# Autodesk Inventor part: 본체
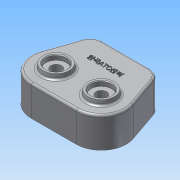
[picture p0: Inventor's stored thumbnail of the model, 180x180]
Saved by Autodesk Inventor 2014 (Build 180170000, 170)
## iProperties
Created: 2014-12
Part Number: 본체
Material: 알루미늄 6061
Document SubType Name: Modeling
Designer: user
Density: 2.71 g/cm^3
Appearance: 알루미늄 - 평지
Mass: 613.436 g
Surface Area: 665.181 cm^2
Volume: 226.36 cm^3
Author: user
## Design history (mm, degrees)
sketch "스케치1"
  geometry: L1 (-47, 0)-(47, 0); L2 (0, -36)-(0, -82); L3 (0, -36)-(-32.527, -68.527); L4 (0, -36)-(32.527, -68.527); L5 (-32.527, -104.527)-(32.527, -104.527); L6 (-66.565, -56.803)-(-47, 0); L7 (66.565, -56.803)-(47, 0); A1 r 46 centre (0, -36) between (0, -82) and (-32.527, -68.527); A2 r 36 centre (-32.527, -68.527) between (-66.565, -56.803) and (-32.527, -104.527); A3 r 36 centre (32.527, -68.527) between (32.527, -104.527) and (66.565, -56.803); A4 r 18 centre (-34.162, -18) between (-34.162, 0) and (-51.181, -12.138); A5 r 18 centre (34.162, -18) between (51.181, -12.138) and (34.162, 0); 2 further points
  constraints: 14 end point, 10 point on circle, 8 tangent, 5 centre point, 4 point on line, 3 coincident, 2 perpendicular, 1 horizontal, 1 midpoint, 1 vertical alignment
  dimensions: "d0" = 94 distance of L1.start L1.end; "d1" = 46 radius of A1; "d2" = 36 distance of L2.start point (0, 0); "d6" = 90 deg angle of L4 L3; "d7" = 45 deg angle of L4 L2; "d8" = 36 radius of A2; "d9" = 36 radius of A3; "d10" = 18 radius of A4; "d11" = 18 radius of A5
extrude "돌출1" new body sketch "스케치1" distance "d12" = 44; taper "d13" = 0 deg
sketch "스케치2"
  geometry: C1 r 20 at (-32.527, -68.527); C2 r 20 at (32.527, -68.527); A1 r 36 centre (-32.527, -68.527) between (-66.565, -56.803) and (-32.527, -104.527) reference; A2 r 36 centre (32.527, -68.527) between (32.527, -104.527) and (66.565, -56.803) reference; 1 further point
  constraints: 2 centre point, 2 coincident
  dimensions: "d14" = 40 diameter of C1; "d15" = 40 diameter of C2
extrude "돌출2" join sketch "스케치2" distance "d16" = 7; taper "d17" = 0 deg
node "작업 평면2"
  node "작업 평면1"
sketch "스케치3"
  geometry: L1 (-20, 44)-(-20, 51) reference; L2 (-20, 44)-(-18.766, 51); L3 (20, 51)-(-20, 51) reference; L4 (0, 51)-(0, 12.352); L5 (-18.654, 44)-(-34.038, 44) reference; L6 (-20, 51)-(-18.766, 51); L7 (-20, 51)-(-20, 44); 1 further point
  constraints: 8 end point, 2 perpendicular, 1 midpoint, 1 point on line
  dimensions: "d19" = 100 deg angle of L2 L5
revolve "회전1" sketch "스케치3" stored, may be unused: angle "d20" = 90 deg
sketch "스케치4"
  geometry: L1 (45.054, 44)-(45.054, 51) reference; L2 (85.054, 51)-(45.054, 51) reference; L3 (45.054, 44)-(46.288, 51); L4 (66.689, 44)-(-1.635, 44) reference; L5 (45.054, 51)-(46.288, 51); L6 (45.054, 51)-(45.054, 44); L7 (65.054, 51)-(65.054, 30.719); 1 further point
  constraints: 8 end point, 1 midpoint, 1 perpendicular, 1 point on line, 1 vertical
  dimensions: "d21" = 100 deg angle of L3 L4
revolve "회전2" sketch "스케치4" stored, may be unused: angle "d22" = 90 deg
sketch "스케치5"
  geometry: L1 (51.181, -12.138)-(66.565, -56.803) reference; L2 (-34.162, 0)-(34.162, 0) reference; L3 (-66.565, -56.803)-(-51.181, -12.138) reference; L4 (32.527, -104.527)-(-32.527, -104.527) reference; L5 (46.453, -13.767)-(61.837, -58.432); L6 (32.527, -99.527)-(-32.527, -99.527); L7 (-61.837, -58.432)-(-46.453, -13.767); L8 (-34.162, -5)-(34.162, -5); A1 r 36 centre (32.527, -68.527) between (32.527, -104.527) and (66.565, -56.803) reference; A2 r 18 centre (34.162, -18) between (51.181, -12.138) and (34.162, 0) reference; A3 r 18 centre (-34.162, -18) between (-34.162, 0) and (-51.181, -12.138) reference; A4 r 36 centre (-32.527, -68.527) between (-66.565, -56.803) and (-32.527, -104.527) reference; A5 r 13 centre (34.162, -18) between (46.453, -13.767) and (34.162, -5); A6 r 31 centre (32.527, -68.527) between (32.527, -99.527) and (61.837, -58.432); A7 r 31 centre (-32.527, -68.527) between (-61.837, -58.432) and (-32.527, -99.527); A8 r 13 centre (-34.162, -18) between (-34.162, -5) and (-46.453, -13.767); 1 further point
  constraints: 8 end point, 8 point on circle, 4 centre point, 7 other
  dimensions: "d23" = 5 distance between parallel lines of L8 L2
extrude "돌출3" cut sketch "스케치5" distance "d24" = 34; taper "d25" = 0 deg
sketch "스케치6"
  geometry: A1 r 36 centre (-32.527, -68.527) between (-66.565, -56.803) and (-32.527, -104.527) reference; A2 r 36 centre (32.527, -68.527) between (32.527, -104.527) and (66.565, -56.803) reference; A3 r 24 centre (-32.527, -68.527) between (-21.111, -47.416) and (-11.416, -57.111); A4 r 24 centre (32.527, -68.527) between (11.416, -57.111) and (21.111, -47.416); A5 r 24 centre (0, -36) between (-11.416, -57.111) and (11.416, -57.111); A6 r 24 centre (0, -36) between (21.111, -47.416) and (-21.111, -47.416); 1 further point
  constraints: 8 point on circle, 4 centre point, 2 coincident, 1 vertical alignment
  dimensions: "d26" = 48 diameter of A3; "d27" = 48 diameter of A4; "d29" = 36 distance of point (0, 0) A5.centre; "d30" = 24 radius of A6; "d31" = 24 radius of A5
extrude "돌출4" join sketch "스케치6" distance "d32" = 11; taper "d33" = 0 deg
sketch "스케치7"
  geometry: L1 (-61.837, -58.432)-(-46.453, -13.767) reference; L2 (32.527, -99.527)-(-32.527, -99.527) reference; L3 (46.453, -13.767)-(61.837, -58.432) reference; A1 r 8 centre (-51.7, -29) between (-54.305, -36.564) and (-49.095, -21.436); A2 r 8 centre (51.7, -29) between (49.095, -21.436) and (54.305, -36.564); A3 r 8 centre (0, -99.527) between (8, -99.527) and (-8, -99.527); 1 further point
  constraints: 8 point on line, 6 point on circle, 3 centre point, 1 midpoint, 1 vertical alignment
  dimensions: "d34" = 8 radius of A1; "d35" = 8 radius of A2; "d36" = 8 radius of A3; "d37" = 29 vertical distance of A2.centre point (0, 0); "d38" = 29 vertical distance of point (0, 0) A1.centre
extrude "돌출5" join sketch "스케치7" stored distance "d39" = 11; taper "d40" = 0 deg
sketch "스케치8"
  geometry: C1 r 17.5 at (-32.527, -68.527); C2 r 17.5 at (32.527, -68.527); A1 r 24 centre (-32.527, -68.527) between (-21.111, -47.416) and (-11.416, -57.111) reference; A2 r 24 centre (32.527, -68.527) between (11.416, -57.111) and (21.111, -47.416) reference; 1 further point
  constraints: 2 centre point, 2 coincident
  dimensions: "d41" = 35 diameter of C1; "d42" = 35 diameter of C2
extrude "돌출6" cut sketch "스케치8" distance "d43" = 11; taper "d44" = 0 deg
sketch "스케치9"
  geometry: C1 r 17.5 at (0, 0) reference; C2 r 17.5 at (65.054, 0) reference; C3 r 15 at (0, 0); C4 r 15 at (65.054, 0); 1 further point
  constraints: 2 centre point, 2 coincident
  dimensions: "d45" = 30 diameter of C3; "d46" = 30 diameter of C4
extrude "돌출7" cut sketch "스케치9" distance "d47" = 7; taper "d48" = 0 deg
sketch "스케치10"
  geometry: C1 r 15 at (0, 0) reference; C2 r 15 at (65.054, 0) reference; C3 r 7.75 at (0, 0); C4 r 7.75 at (65.054, 0); 1 further point
  constraints: 2 centre point, 2 coincident
  dimensions: "d49" = 15.5 diameter of C3; "d50" = 15.5 diameter of C4
extrude "돌출8" cut sketch "스케치10" stored distance "d51" = 7; taper "d52" = 0 deg
sketch "스케치11"
  geometry: C1 r 20 at (0, -36); A1 r 24 centre (0, -36) between (21.111, -47.416) and (-21.111, -47.416) reference; 1 further point
  constraints: 1 centre point, 1 coincident
  dimensions: "d53" = 40 diameter of C1
extrude "돌출9" cut sketch "스케치11" distance "d54" = 12; taper "d55" = 0 deg
sketch "스케치12"
  geometry: C1 r 20 at (0, 0) reference; C2 r 10 at (0, 0); 1 further point
  constraints: 1 centre point, 1 coincident
  dimensions: "d56" = 20 diameter of C2
extrude "돌출10" cut sketch "스케치12" distance "d57" = 3; taper "d58" = 0 deg
fillet "모깎기1" dims "d59" = 3
sketch "스케치13"
  geometry: L1 (34.162, 0)-(-34.162, 0) reference; 3 further points
  constraints: 1 midpoint, 1 vertical alignment, 1 other
  dimensions: "d60" = 30 distance of point (0, -30) point (0, 0)
feature "엠보싱1" sketch "스케치13" dims "d61" = 1, "d62" = 0
fillet "모깎기2" dims "d63" = 3
fillet "모깎기3" dims "d64" = 3
fillet "모깎기4" dims "d65" = 3
fillet "모깎기5" dims "d66" = 3
fillet "모깎기7" dims "d68" = 3
fillet "모깎기8" dims "d69" = 3
chamfer "모따기1" distance "d70" = 1; stored, may be unused: second distance "d71" = 2, angle "d72" = 45 deg
fillet "모깎기9" dims "d73" = 0.3
fillet "모깎기10" dims "d74" = 0.1
sketch "스케치15"
  geometry: A1 r 8 centre (-51.7, -29) between (-52.144, -36.988) and (-47.131, -22.433) reference; A2 r 8 centre (51.7, -29) between (47.131, -22.433) and (52.144, -36.988) reference; A3 r 8 centre (0, -99.527) between (7.697, -97.345) and (-7.697, -97.345) reference; 4 further points
  constraints: 3 coincident
hole "구멍1" sketch "스케치15" at (-51.7, -29), (0, -99.527), (51.7, -29) diameter "d75" = 4.134; stored, may be unused: countersink angle "d79" = 90 deg, drill point angle "d81" = 118 deg; dims "d76" = 20, "d77" = 4, "d78" = 2, "d80" = 23
node "솔리드1"
node "투영된 루프1"
node "투영된 루프2"
node "투영된 루프3"
node "투영된 루프4"
node "투영된 루프5"
node "투영된 루프6"
other parameters: "d18" = -36, "d28" = 48
